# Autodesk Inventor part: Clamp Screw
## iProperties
Shininess: 41.0
Length Units: 11272
Angle Units: 11279
Time Units: 11290
Mass Units: 11286
Length Display Precision: 4
Angle Display Precision: 2
Compacted: True
Manager: Lebovitz
Company: Autodesk
Created: 2000-11
Part Number: Clamp Screw
Document SubType Name: Modeling
Designer: The PD Team
Project: Inventor Samples
Density: 0.0
Volumn: 0.0
Area: 0.0
PropertySet Name: Model Information
Control State: 0
Master: False
Checked Out: False
Author: The PD Team
Revision Number: A
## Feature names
1. Extrusion1
2. Extrusion2
3. Extrusion3
4. Chamfer1
